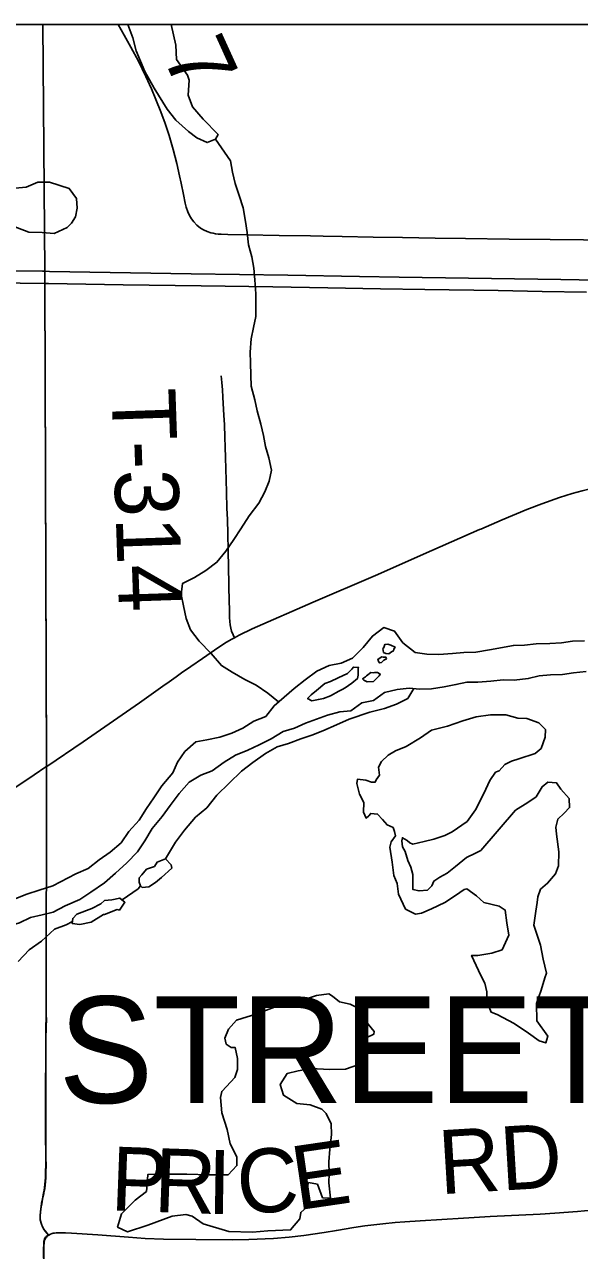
# Model space of a CAD drawing. Extents: x 0 to 34, y 0 to 22.
# Drawn here: x 5.003 to 5.497, y 19.806 to 20.9 of the extents above; entities that cross this region are included whole.
import ezdxf

# ---------------------------------------------------------------- set-up
doc = ezdxf.new("R2010")
doc.units = 0
for name, color, linetype in [('GM_X_Corporation', 7, 'Continuous'), ('GM_X_Corporation_Text', 7, 'Continuous'), ('GM_X_County_Road', 7, 'Continuous'), ('GM_X_Interstate_Route', 7, 'Continuous'), ('GM_X_Major_River', 7, 'Continuous'), ('GM_X_Minor_Lake', 7, 'Continuous'), ('GM_X_Minor_River', 7, 'Continuous'), ('GM_X_State_Route', 7, 'Continuous'), ('GM_X_Township_Road', 7, 'Continuous'), ('GM_X_Township_Road_Text', 7, 'Continuous'), ('SH_Data', 7, 'Continuous')]:
    doc.layers.add(name, color=color, linetype=linetype)

msp = doc.modelspace()

# ---------------------------------------------------------------- linework, layer by layer
at = {"layer": 'GM_X_Corporation'}
for points in [[(5.0203, 19.8037), (5.0204, 19.8126), (5.0205, 19.8156), (5.0206, 19.8172), (5.0207, 19.8184), (5.0209, 19.8195), (5.0213, 19.8209), (5.0218, 19.8217), (5.0221, 19.8222), (5.0227, 19.8229), (5.0234, 19.8236), (5.0241, 19.8243), (5.0247, 19.8247), (5.0233, 19.8263), (5.0215, 19.8282), (5.0207, 19.8295), (5.0198, 19.831), (5.0191, 19.8325), (5.0186, 19.8337), (5.0178, 19.8361), (5.0174, 19.8378), (5.0172, 19.8394), (5.0172, 19.8406), (5.0172, 19.8419), (5.0175, 19.8449), (5.0178, 19.8478), (5.0181, 19.8497), (5.0185, 19.8525), (5.0193, 19.8565), (5.0203, 19.8617), (5.0208, 19.8641), (5.0212, 19.8662), (5.0216, 19.8693), (5.0219, 19.8721), (5.0221, 19.8756), (5.0222, 19.8804), (5.0224, 19.8869), (5.0223, 19.893), (5.0222, 19.9148), (5.0222, 19.942), (5.0222, 19.9534), (5.0223, 19.9842), (5.0223, 19.9935), (5.0223, 20.0003), (5.0225, 20.0084), (5.0226, 20.0182), (5.023, 20.2413), (5.023, 20.2443), (5.0214, 20.6704), (5.0214, 20.6813), (5.0198, 20.9), (2.1, 20.9)], [(5.0203, 19.8037), (5.0204, 19.8126), (5.0205, 19.8156), (5.0206, 19.8172), (5.0207, 19.8184), (5.0209, 19.8195), (5.0213, 19.8209), (5.0218, 19.8217), (5.0221, 19.8222), (5.0227, 19.8229), (5.0234, 19.8236), (5.0241, 19.8243), (5.0247, 19.8247), (5.0233, 19.8263), (5.0215, 19.8282), (5.0207, 19.8295), (5.0198, 19.831), (5.0191, 19.8325), (5.0186, 19.8337), (5.0178, 19.8361), (5.0174, 19.8378), (5.0172, 19.8394), (5.0172, 19.8406), (5.0172, 19.8419), (5.0175, 19.8449), (5.0178, 19.8478), (5.0181, 19.8497), (5.0185, 19.8525), (5.0193, 19.8565), (5.0203, 19.8617), (5.0208, 19.8641), (5.0212, 19.8662), (5.0216, 19.8693), (5.0219, 19.8721), (5.0221, 19.8756), (5.0222, 19.8804), (5.0224, 19.8869), (5.0223, 19.893), (5.0222, 19.9148), (5.0222, 19.942), (5.0222, 19.9534), (5.0223, 19.9842), (5.0223, 19.9935), (5.0223, 20.0003), (5.0225, 20.0084), (5.0226, 20.0182), (5.023, 20.2413), (5.0214, 20.6704), (5.0214, 20.6813), (5.0198, 20.9), (2.1, 20.9)], [(8.9, 20.9), (5.0198, 20.9), (5.0214, 20.6813), (5.0214, 20.6704), (5.023, 20.2413), (5.0226, 20.0182), (5.0225, 20.0084), (5.0223, 20.0003), (5.0223, 19.9935), (5.0223, 19.9842), (5.0222, 19.9534), (5.0222, 19.942), (5.0222, 19.9148), (5.0223, 19.893), (5.0224, 19.8869), (5.0222, 19.8804), (5.0221, 19.8756), (5.0219, 19.8721), (5.0216, 19.8693), (5.0212, 19.8662), (5.0208, 19.8641), (5.0203, 19.8617), (5.0193, 19.8565), (5.0185, 19.8525), (5.0181, 19.8497), (5.0178, 19.8478), (5.0175, 19.8449), (5.0172, 19.8419), (5.0172, 19.8406), (5.0172, 19.8394), (5.0174, 19.8378), (5.0178, 19.8361), (5.0186, 19.8337), (5.0191, 19.8325), (5.0198, 19.831), (5.0207, 19.8295), (5.0215, 19.8282), (5.0233, 19.8263), (5.0247, 19.8247), (5.0241, 19.8243), (5.0234, 19.8236), (5.0227, 19.8229), (5.0221, 19.8222), (5.0218, 19.8217), (5.0213, 19.8209), (5.0209, 19.8195), (5.0207, 19.8184), (5.0206, 19.8172), (5.0205, 19.8156), (5.0204, 19.8126), (5.0203, 19.8037)]]:
    msp.add_lwpolyline(points, dxfattribs=at)
at = {"layer": 'GM_X_County_Road'}
for points in [[(5.409, 20.4516), (5.428, 20.4599), (5.4499, 20.469), (5.4633, 20.4741), (5.4791, 20.4798), (5.4901, 20.4834), (5.499, 20.4857), (5.5096, 20.4883), (5.5166, 20.4896), (5.5201, 20.4901)], [(5.1901, 20.3551), (5.1941, 20.3573), (5.2059, 20.3629), (5.26, 20.3867), (5.3154, 20.4104), (5.3655, 20.4325), (5.408, 20.4512), (5.409, 20.4516)], [(5.0224, 20.2402), (5.0232, 20.2407), (5.0555, 20.2627), (5.0863, 20.2838), (5.1056, 20.2973), (5.1264, 20.312), (5.132, 20.316), (5.1381, 20.3203), (5.1431, 20.3239), (5.1513, 20.3296), (5.1615, 20.3367), (5.1722, 20.3441), (5.1816, 20.3502), (5.187, 20.3534), (5.1901, 20.3551)], [(4.7633, 20.0106), (4.7691, 20.0148), (4.773, 20.0178), (4.7763, 20.0206), (4.7813, 20.0252), (4.7847, 20.0285), (4.829, 20.0758), (4.8792, 20.1301), (4.8947, 20.1463), (4.9015, 20.1528), (4.907, 20.1578), (4.9141, 20.1639), (4.9296, 20.1763), (4.9386, 20.1831), (4.9492, 20.1907), (4.9717, 20.2063), (4.981, 20.2125), (4.9939, 20.2212), (5.0119, 20.2333), (5.0224, 20.2402)]]:
    msp.add_lwpolyline(points, dxfattribs=at)
at = {"layer": 'GM_X_Interstate_Route'}
for points in [[(4.3537, 20.713), (4.3787, 20.7092), (4.4004, 20.7063), (4.4267, 20.7028), (4.4555, 20.6994), (4.4747, 20.6972), (4.4897, 20.6958), (4.5108, 20.6939), (4.5291, 20.6925), (4.5687, 20.6896), (4.5899, 20.6884), (4.6135, 20.6873), (4.6302, 20.6871), (4.6969, 20.686), (4.7472, 20.685), (4.7845, 20.6843), (4.8567, 20.6833), (4.9092, 20.6824), (4.9936, 20.6812), (5.0193, 20.6808), (5.0216, 20.6808), (5.0256, 20.6807)], [(4.3515, 20.7028), (4.3825, 20.6982), (4.3999, 20.6956), (4.4285, 20.6916), (4.4465, 20.6893), (4.4765, 20.6863), (4.5122, 20.6832), (4.5529, 20.6805), (4.583, 20.6783), (4.5979, 20.6775), (4.6198, 20.6768), (4.6453, 20.6758), (4.6707, 20.6752), (4.6999, 20.6747), (4.724, 20.6743), (4.7463, 20.674), (4.8223, 20.673), (4.8727, 20.6722), (4.925, 20.6714), (4.9714, 20.6707), (4.9996, 20.6702), (5.0216, 20.6698), (5.0246, 20.6698)], [(5.0256, 20.6807), (5.1515, 20.6786), (5.2376, 20.6772), (5.3013, 20.6761), (5.3365, 20.6756), (5.4801, 20.6735), (5.5288, 20.6727)], [(5.0246, 20.6698), (5.0911, 20.6688), (5.1603, 20.6678), (5.224, 20.6669), (5.273, 20.666), (5.3199, 20.6652), (5.3594, 20.6646), (5.4244, 20.6636), (5.4637, 20.6629), (5.5031, 20.6623)]]:
    msp.add_lwpolyline(points, dxfattribs=at)
at = {"layer": 'GM_X_Major_River'}
for p, q in [((5.3206, 20.3331), (5.3229, 20.335)), ((5.3272, 20.3407), (5.3295, 20.3426)), ((5.3137, 20.3163), (5.3186, 20.3212)), ((5.2755, 20.3034), (5.2827, 20.3077))]:
    msp.add_line(p, q, dxfattribs=at)
for points in [[(5.5012, 20.3522), (5.4906, 20.3521), (5.4808, 20.3506), (5.4705, 20.3501), (5.4581, 20.3496), (5.4478, 20.3484), (5.438, 20.3483), (5.4168, 20.3444), (5.4047, 20.3424), (5.3938, 20.3419), (5.3839, 20.3411), (5.3718, 20.3402), (5.3609, 20.3405), (5.3506, 20.342), (5.3396, 20.3506), (5.3323, 20.3608), (5.3228, 20.3641), (5.3127, 20.3565), (5.3044, 20.3465), (5.295, 20.337), (5.2848, 20.3324), (5.2743, 20.3304), (5.2633, 20.3254), (5.2528, 20.3177), (5.243, 20.31), (5.2253, 20.2947), (5.2178, 20.2852), (5.2073, 20.2809), (5.1975, 20.2748), (5.1877, 20.2702), (5.1771, 20.2667), (5.1654, 20.2643), (5.1556, 20.2627), (5.1458, 20.2539), (5.1394, 20.2444), (5.1353, 20.2349), (5.1256, 20.2234), (5.1185, 20.2127), (5.1117, 20.2032), (5.1054, 20.1929), (5.096, 20.183), (5.0893, 20.1727), (5.0795, 20.1646), (5.0697, 20.1577), (5.0599, 20.1501), (5.049, 20.1451), (5.0286, 20.1347), (5.0165, 20.1308), (5.0056, 20.1273), (4.9958, 20.1234)], [(5.3295, 20.3426), (5.3313, 20.3434), (5.3317, 20.3449), (5.3328, 20.3468), (5.329, 20.3486), (5.3263, 20.3494), (5.3237, 20.349), (5.323, 20.3474), (5.3226, 20.3459), (5.3218, 20.3455), (5.3226, 20.3421), (5.3245, 20.341), (5.3272, 20.3407)], [(5.3229, 20.335), (5.3251, 20.3362), (5.3247, 20.3377), (5.3225, 20.3377), (5.3209, 20.3381), (5.3179, 20.3361), (5.3176, 20.335), (5.3191, 20.3327), (5.3206, 20.3331)], [(5.1703, 20.2369), (5.1809, 20.2446), (5.191, 20.2508), (5.2019, 20.2551), (5.2121, 20.2598), (5.2227, 20.2652), (5.2332, 20.2718), (5.2434, 20.2746), (5.2532, 20.2792), (5.2728, 20.2863), (5.2837, 20.2891), (5.2936, 20.29), (5.3034, 20.2973), (5.3136, 20.2993), (5.3233, 20.3063), (5.3347, 20.309), (5.3452, 20.3103), (5.3547, 20.3093), (5.3653, 20.3098), (5.3763, 20.3114), (5.3869, 20.3135), (5.3967, 20.3155), (5.4065, 20.3156), (5.4179, 20.3165), (5.4289, 20.3177), (5.4387, 20.3175), (5.4512, 20.3188), (5.461, 20.3212), (5.4709, 20.322), (5.4815, 20.3225), (5.4913, 20.3238), (5.5026, 20.3251)], [(5.2827, 20.3077), (5.2857, 20.3092), (5.2883, 20.3107), (5.2944, 20.3146), (5.2993, 20.3188), (5.3, 20.3218), (5.3, 20.3283), (5.3003, 20.3287), (5.2958, 20.329), (5.2943, 20.3271), (5.2905, 20.3233), (5.2822, 20.3194), (5.2754, 20.3163), (5.2705, 20.3144), (5.263, 20.3083), (5.2581, 20.3044), (5.2551, 20.301), (5.2589, 20.2991), (5.2646, 20.3003), (5.2691, 20.3011), (5.2755, 20.3034)], [(5.3186, 20.3212), (5.3197, 20.3228), (5.3171, 20.3243), (5.3148, 20.3242), (5.3137, 20.3239), (5.3114, 20.3242), (5.3073, 20.3212), (5.3065, 20.3204), (5.3039, 20.3185), (5.305, 20.3173), (5.3081, 20.3159), (5.3137, 20.3163)], [(4.955, 20.0888), (4.9669, 20.0932), (4.9767, 20.0967), (4.9892, 20.0987), (4.999, 20.1018), (5.0088, 20.1064), (5.019, 20.1088), (5.0288, 20.1112), (5.0394, 20.1169), (5.0526, 20.1223), (5.0624, 20.1289), (5.0744, 20.1373), (5.0842, 20.1457), (5.0943, 20.1549), (5.1037, 20.1648), (5.1104, 20.1747), (5.1168, 20.1854), (5.1258, 20.1961), (5.1329, 20.206), (5.1408, 20.2167), (5.1498, 20.2266), (5.16, 20.2328), (5.1703, 20.2369)]]:
    msp.add_lwpolyline(points, dxfattribs=at)
at = {"layer": 'GM_X_Minor_Lake'}
for p, q in [((5.4399, 20.2019), (5.4091, 20.166)), ((5.119, 20.1517), (5.1118, 20.1493)), ((5.0711, 20.1187), (5.0632, 20.1145)), ((5.2749, 19.9006), (5.2763, 19.9135))]:
    msp.add_line(p, q, dxfattribs=at)
for points in [[(5.0953, 20.9), (5.0997, 20.8882), (5.1027, 20.8768), (5.1104, 20.8583), (5.1188, 20.8435), (5.1303, 20.825), (5.1379, 20.8152), (5.1493, 20.805), (5.1566, 20.7993), (5.1657, 20.7952), (5.1732, 20.7983), (5.1755, 20.8024), (5.1622, 20.816), (5.1526, 20.827), (5.1488, 20.8372), (5.1499, 20.8505), (5.1483, 20.8551), (5.1384, 20.869), (5.138, 20.8816), (5.1337, 20.9)], [(4.9578, 20.7304), (4.9696, 20.7271), (4.9908, 20.7219), (5.0071, 20.7156), (5.0192, 20.7153), (5.0298, 20.7143), (5.0412, 20.7197), (5.0453, 20.7235), (5.0486, 20.7292), (5.0501, 20.7368), (5.0497, 20.7455), (5.0432, 20.7542), (5.0257, 20.7601), (5.0151, 20.76), (5.0049, 20.7554), (4.9951, 20.7546), (4.989, 20.7583)], [(5.4091, 20.166), (5.4042, 20.1637), (5.3963, 20.1599), (5.3865, 20.1518), (5.379, 20.1457), (5.3726, 20.1422), (5.3673, 20.1388), (5.3655, 20.1346), (5.3617, 20.1308), (5.3542, 20.13), (5.3485, 20.1314), (5.3487, 20.1447), (5.3468, 20.1512), (5.3441, 20.1572), (5.3418, 20.1651), (5.3395, 20.1693), (5.3387, 20.1746), (5.3394, 20.1773), (5.3436, 20.175), (5.3459, 20.1728), (5.3485, 20.1716), (5.3587, 20.174), (5.3674, 20.176), (5.3769, 20.1794), (5.3836, 20.1825), (5.3968, 20.1917), (5.4043, 20.202), (5.4118, 20.2165), (5.417, 20.2283), (5.4222, 20.2356), (5.4252, 20.2367), (5.4305, 20.2424), (5.4362, 20.2455), (5.4429, 20.2475), (5.4573, 20.2521), (5.4626, 20.2567), (5.4663, 20.2666), (5.4666, 20.2734), (5.4605, 20.2795), (5.4499, 20.2832), (5.4419, 20.2835), (5.4313, 20.2865), (5.4177, 20.2867), (5.4048, 20.2847), (5.3931, 20.2812), (5.3795, 20.2766), (5.3652, 20.273), (5.3554, 20.2661), (5.3426, 20.2585), (5.3331, 20.2546), (5.3267, 20.2508), (5.3207, 20.245), (5.3181, 20.2401), (5.3189, 20.2329), (5.3159, 20.2287), (5.3152, 20.2268), (5.3118, 20.2267), (5.3068, 20.2286), (5.2993, 20.2293), (5.2989, 20.2255), (5.3013, 20.216), (5.3051, 20.2085), (5.3048, 20.2001), (5.3071, 20.1948), (5.3094, 20.1968), (5.3112, 20.199), (5.3173, 20.1983), (5.3215, 20.1934), (5.3257, 20.1889), (5.331, 20.1863), (5.3322, 20.1829), (5.3333, 20.1791), (5.3292, 20.1738), (5.3281, 20.1688), (5.3301, 20.1556), (5.3317, 20.1438), (5.3348, 20.1366), (5.336, 20.1272), (5.3422, 20.1139), (5.3509, 20.1095), (5.3562, 20.1103), (5.3653, 20.1141), (5.3769, 20.1199), (5.3864, 20.126), (5.3943, 20.1314), (5.3965, 20.1318), (5.4053, 20.1258), (5.4118, 20.1198), (5.4254, 20.1165), (5.4307, 20.1131), (5.4323, 20.1017), (5.4339, 20.0908), (5.428, 20.0778), (5.4189, 20.0747), (5.4064, 20.0727), (5.4008, 20.0727), (5.4089, 20.0549)], [(5.4089, 20.0549), (5.4127, 20.0481), (5.4143, 20.0405), (5.4147, 20.0311), (5.4182, 20.0224), (5.4235, 20.0201), (5.4387, 20.0123), (5.4513, 20.0036), (5.4608, 19.9969), (5.4668, 19.995), (5.4687, 20.0011), (5.4587, 20.0147), (5.4586, 20.0299), (5.4627, 20.042), (5.466, 20.0527), (5.4675, 20.0569), (5.4644, 20.0694), (5.462, 20.0819), (5.4562, 20.0996), (5.458, 20.1122), (5.4591, 20.1198), (5.4598, 20.1247), (5.462, 20.1316), (5.4684, 20.1369), (5.4755, 20.1453), (5.4781, 20.1525), (5.4784, 20.1647), (5.4764, 20.1806), (5.4756, 20.1867), (5.4774, 20.1939), (5.4831, 20.1992), (5.4879, 20.2042), (5.4875, 20.2122), (5.4802, 20.2205), (5.4764, 20.2261), (5.4685, 20.2268), (5.4636, 20.2226), (5.4583, 20.2138), (5.4508, 20.2085), (5.4399, 20.2019)], [(5.1118, 20.1493), (5.1077, 20.1444), (5.1054, 20.1417), (5.1054, 20.1379), (5.1066, 20.1345), (5.1081, 20.133), (5.1138, 20.1338), (5.1198, 20.1376), (5.1251, 20.1419), (5.1345, 20.1503), (5.1337, 20.1533), (5.1287, 20.1586), (5.1212, 20.1555), (5.119, 20.1517)], [(5.0632, 20.1145), (5.05, 20.1094), (5.0463, 20.1056), (5.0459, 20.101), (5.0527, 20.1003), (5.0626, 20.1023), (5.0735, 20.1092), (5.0746, 20.1092), (5.0859, 20.1135), (5.0878, 20.1131), (5.0927, 20.12), (5.09, 20.1222), (5.0881, 20.1237), (5.081, 20.1222), (5.0745, 20.1214), (5.0711, 20.1187)], [(5.2763, 19.9135), (5.2759, 19.923), (5.2717, 19.9321), (5.2678, 19.9362), (5.2572, 19.9399), (5.2455, 19.941), (5.2337, 19.9485), (5.2306, 19.958), (5.2369, 19.9679), (5.2468, 19.9702), (5.2581, 19.9722), (5.2744, 19.9712), (5.2888, 19.9717), (5.3005, 19.9759), (5.3049, 19.9847), (5.306, 19.9889), (5.306, 19.9942), (5.3071, 19.9995), (5.3139, 20.0026), (5.3142, 20.0052), (5.3089, 20.0117), (5.3043, 20.0192), (5.2982, 20.0267), (5.2929, 20.0294), (5.2834, 20.0316), (5.2773, 20.0364), (5.2739, 20.0387), (5.2629, 20.0371), (5.255, 20.0344), (5.2414, 20.032), (5.2334, 20.0304), (5.2255, 20.0266), (5.21, 20.0208), (5.1919, 20.0153), (5.1848, 20.0073), (5.1814, 19.9993), (5.1826, 19.994), (5.1872, 19.991), (5.1906, 19.991), (5.1926, 19.9812), (5.1926, 19.9713), (5.1904, 19.9641), (5.1829, 19.9561), (5.1788, 19.9519), (5.1777, 19.9465), (5.1789, 19.9329), (5.1836, 19.9181), (5.1863, 19.9053), (5.1921, 19.8936), (5.1922, 19.886), (5.1843, 19.8776), (5.1676, 19.8778), (5.1476, 19.8784), (5.1286, 19.8783), (5.1131, 19.8781), (5.1124, 19.869), (5.1117, 19.863), (5.1019, 19.8553), (5.0895, 19.8431), (5.0862, 19.8313), (5.095, 19.8272), (5.1131, 19.833), (5.1346, 19.8411), (5.1467, 19.8424), (5.1524, 19.8409), (5.1623, 19.8341), (5.185, 19.8275), (5.2062, 19.8269), (5.2198, 19.8281), (5.2399, 19.8287), (5.2482, 19.8386), (5.2489, 19.8443), (5.2553, 19.85), (5.2529, 19.861), (5.2559, 19.8709), (5.2638, 19.8694), (5.2684, 19.8573), (5.2753, 19.857), (5.274, 19.8707), (5.2743, 19.879), (5.2739, 19.8892), (5.2749, 19.9006)]]:
    msp.add_lwpolyline(points, dxfattribs=at)
at = {"layer": 'GM_X_Minor_River'}
for points in [[(5.1732, 20.7983), (5.1864, 20.7788), (5.1884, 20.769), (5.1907, 20.7587), (5.1942, 20.7481), (5.1977, 20.7372), (5.1997, 20.7251), (5.2013, 20.7152), (5.2025, 20.7042), (5.2056, 20.6936), (5.2072, 20.6834), (5.208, 20.6731), (5.2089, 20.6606), (5.2091, 20.6405), (5.2069, 20.6307), (5.205, 20.6208), (5.204, 20.609), (5.2044, 20.5995), (5.2045, 20.5885), (5.205, 20.5787), (5.2081, 20.5666), (5.2101, 20.5567), (5.2136, 20.545), (5.2159, 20.5348), (5.2175, 20.5249), (5.2206, 20.5151), (5.223, 20.5041), (5.2208, 20.4942), (5.2171, 20.4847), (5.2118, 20.4748), (5.2032, 20.4634), (5.1957, 20.4519), (5.1894, 20.4424), (5.1823, 20.4321), (5.1744, 20.4222), (5.1646, 20.4149), (5.1544, 20.4087), (5.1439, 20.4033), (5.1428, 20.3935), (5.1448, 20.3833), (5.1472, 20.3723), (5.151, 20.3621), (5.1587, 20.3519), (5.1693, 20.341), (5.1785, 20.3304), (5.188, 20.3244), (5.1994, 20.3181), (5.2093, 20.3128), (5.2196, 20.3057), (5.2293, 20.2982)], [(5.1287, 20.1586), (5.1377, 20.1734), (5.1456, 20.1841), (5.1553, 20.1956), (5.1655, 20.204), (5.1745, 20.2151), (5.1963, 20.2365), (5.2064, 20.2441), (5.2177, 20.2522), (5.2279, 20.258), (5.2381, 20.2611), (5.249, 20.2653), (5.2588, 20.2684), (5.2687, 20.2723), (5.2807, 20.2777), (5.292, 20.2827), (5.3105, 20.2889), (5.3234, 20.2921), (5.334, 20.2959), (5.3441, 20.301), (5.3494, 20.3099)], [(5.0902, 20.1221), (5.1044, 20.1319), (5.1066, 20.1345)], [(4.9977, 20.0673), (5.0075, 20.0776), (5.0184, 20.0853), (5.0301, 20.096), (5.0403, 20.0999), (5.0461, 20.1028)]]:
    msp.add_lwpolyline(points, dxfattribs=at)
at = {"layer": 'GM_X_State_Route'}
for points in [[(5.409, 20.4516), (5.428, 20.4599), (5.4499, 20.469), (5.4633, 20.4741), (5.4791, 20.4798), (5.4901, 20.4834), (5.499, 20.4857), (5.5096, 20.4883), (5.5166, 20.4896), (5.5201, 20.4901)], [(5.1901, 20.3551), (5.1941, 20.3573), (5.2059, 20.3629), (5.26, 20.3867), (5.3154, 20.4104), (5.3655, 20.4325), (5.408, 20.4512), (5.409, 20.4516)], [(5.0224, 20.2402), (5.0232, 20.2407), (5.0555, 20.2627), (5.0863, 20.2838), (5.1056, 20.2973), (5.1264, 20.312), (5.132, 20.316), (5.1381, 20.3203), (5.1431, 20.3239), (5.1513, 20.3296), (5.1615, 20.3367), (5.1722, 20.3441), (5.1816, 20.3502), (5.187, 20.3534), (5.1901, 20.3551)], [(4.7633, 20.0106), (4.7691, 20.0148), (4.773, 20.0178), (4.7763, 20.0206), (4.7813, 20.0252), (4.7847, 20.0285), (4.829, 20.0758), (4.8792, 20.1301), (4.8947, 20.1463), (4.9015, 20.1528), (4.907, 20.1578), (4.9141, 20.1639), (4.9296, 20.1763), (4.9386, 20.1831), (4.9492, 20.1907), (4.9717, 20.2063), (4.981, 20.2125), (4.9939, 20.2212), (5.0119, 20.2333), (5.0224, 20.2402)]]:
    msp.add_lwpolyline(points, dxfattribs=at)
at = {"layer": 'GM_X_Township_Road'}
for points in [[(5.0866, 20.9), (5.0919, 20.8907), (5.098, 20.8799), (5.1046, 20.8676), (5.1113, 20.8538), (5.1163, 20.8428), (5.1202, 20.8335), (5.1246, 20.8225), (5.1284, 20.8121), (5.1319, 20.8015), (5.1355, 20.7889), (5.1388, 20.7766), (5.1413, 20.7656), (5.1427, 20.759), (5.1446, 20.7489), (5.1463, 20.7412), (5.1471, 20.7379), (5.1485, 20.7337), (5.1501, 20.7303), (5.1518, 20.7275), (5.154, 20.7247), (5.1566, 20.7218), (5.1598, 20.7192), (5.1625, 20.7175), (5.1659, 20.716), (5.1689, 20.715), (5.1712, 20.7145), (5.1732, 20.7141), (5.1754, 20.7139), (5.1783, 20.7137), (5.1841, 20.7135), (5.2011, 20.7132), (5.2298, 20.7127), (5.2577, 20.7122), (5.2688, 20.7119)], [(5.2688, 20.7119), (5.2859, 20.7116), (5.3133, 20.7112), (5.3395, 20.7108), (5.3685, 20.7103), (5.3953, 20.7099), (5.4341, 20.7094), (5.4706, 20.7089), (5.5004, 20.7086), (5.5332, 20.7082), (5.5407, 20.7081), (5.545, 20.7078), (5.5493, 20.7073), (5.5529, 20.7067), (5.5578, 20.7054)], [(5.1901, 20.3551), (5.1889, 20.3577), (5.1875, 20.3608), (5.1867, 20.3635), (5.1861, 20.3665), (5.1858, 20.3696), (5.1857, 20.3732), (5.1857, 20.3775), (5.1856, 20.3817), (5.1854, 20.3861), (5.1853, 20.3916), (5.1851, 20.3969), (5.1849, 20.4031), (5.1846, 20.4174), (5.1843, 20.4325), (5.184, 20.4474), (5.1837, 20.4601), (5.1834, 20.4701), (5.1831, 20.4845), (5.1828, 20.4951), (5.1822, 20.5153), (5.1819, 20.5245), (5.1816, 20.5332), (5.1811, 20.5442), (5.1807, 20.553), (5.1801, 20.5634), (5.1798, 20.5689), (5.1793, 20.5753), (5.1788, 20.5819), (5.1783, 20.5879)], [(5.0249, 19.8241), (5.0235, 19.8257), (5.0217, 19.8277), (5.0209, 19.8289), (5.02, 19.8304), (5.0193, 19.8319), (5.0188, 19.8331), (5.018, 19.8356), (5.0176, 19.8372), (5.0174, 19.8389), (5.0174, 19.84), (5.0174, 19.8413), (5.0177, 19.8443), (5.018, 19.8473), (5.0183, 19.8492), (5.0187, 19.852), (5.0195, 19.856), (5.0205, 19.8611), (5.021, 19.8636), (5.0214, 19.8657), (5.0218, 19.8688), (5.0221, 19.8716), (5.0223, 19.875), (5.0224, 19.8799), (5.0226, 19.8864), (5.0225, 19.8925), (5.0224, 19.9142), (5.0224, 19.9324), (5.0224, 19.9415), (5.0224, 19.9528), (5.0225, 19.9837), (5.0225, 19.9929), (5.0225, 19.9997), (5.0227, 20.0078), (5.0228, 20.0177)], [(5.0249, 19.8241), (5.0266, 19.825), (5.0279, 19.8255), (5.029, 19.8258), (5.0302, 19.826), (5.0316, 19.8262), (5.0332, 19.8262), (5.0346, 19.8262), (5.0397, 19.8261), (5.0451, 19.8259), (5.0686, 19.8243), (5.0959, 19.8222), (5.1108, 19.8212), (5.127, 19.8205), (5.1556, 19.8202), (5.1885, 19.8201), (5.2028, 19.8203), (5.2246, 19.8212), (5.2388, 19.8223), (5.2518, 19.8237), (5.2697, 19.8265), (5.2807, 19.8284), (5.296, 19.8309), (5.3058, 19.8324), (5.3218, 19.8343), (5.3329, 19.8353), (5.3415, 19.8359), (5.3552, 19.8368), (5.3936, 19.8391), (5.4172, 19.8406), (5.4618, 19.8429), (5.4749, 19.8436), (5.4951, 19.845), (5.5075, 19.8462)], [(5.0205, 19.8031), (5.0206, 19.812), (5.0207, 19.8151), (5.0208, 19.8167), (5.0209, 19.8178), (5.0211, 19.819), (5.0216, 19.8203), (5.022, 19.8212), (5.0223, 19.8217), (5.0229, 19.8224), (5.0236, 19.8231), (5.0243, 19.8237), (5.0249, 19.8241)]]:
    msp.add_lwpolyline(points, dxfattribs=at)
at = {"layer": 'SH_Data'}
msp.add_line((2.1, 20.9), (8.9, 20.9), dxfattribs=at)

# ---------------------------------------------------------------- texts
at = {"layer": 'GM_X_Corporation_Text'}
msp.add_text('STREETSBORO', height=0.094697, rotation=0, dxfattribs=at).set_placement((5.0335, 19.9416))
at = {"layer": 'GM_X_Township_Road_Text'}
for s, height, rotation, p in [('7', 0.0568, 294.425, (5.1254, 20.8728)), ('T-314', 0.05682, 271.9435, (5.0807, 20.5757)), ('RD', 0.05682, 3.4521, (5.373, 19.8604)), ('E', 0.0568, 8.3339, (5.2456, 19.8461)), ('P', 0.0568, 357.8518, (5.0794, 19.8462)), ('R', 0.0568, 357.9925, (5.1179, 19.8448)), ('I', 0.0568, 359.0125, (5.1656, 19.8431)), ('C', 0.0568, 3.4396, (5.1937, 19.8428))]:
    msp.add_text(s, height=height, rotation=rotation, dxfattribs=at).set_placement(p)

doc.saveas('drawing.dxf')
